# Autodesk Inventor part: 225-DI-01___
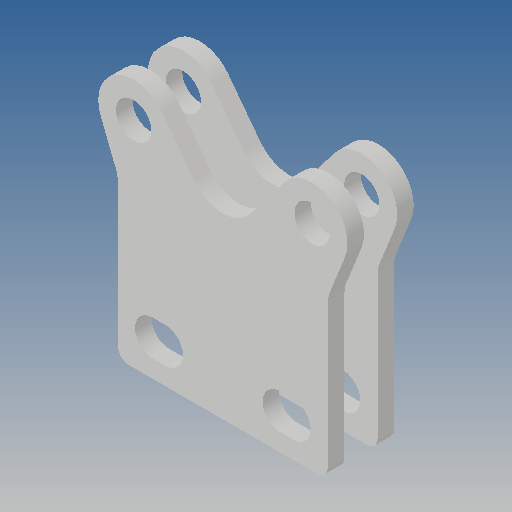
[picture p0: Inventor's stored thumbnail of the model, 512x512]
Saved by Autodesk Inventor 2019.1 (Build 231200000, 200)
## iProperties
Created: 2013-01
Part Number: 225-DI-01___
Material: Ogólny
Document SubType Name: Modeling
Designer: CADENGINEERING4
Density: 1 g/cm^3
Appearance: Domyślna
Author: CADENGINEERING4
Revision Number: ÈÎºÎ
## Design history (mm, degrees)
feature "NONE" [ÊäÈë]
feature "ÊäÈë2"
node "Bryła1"
node "Bryła2"
